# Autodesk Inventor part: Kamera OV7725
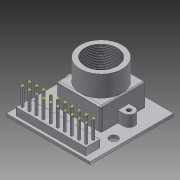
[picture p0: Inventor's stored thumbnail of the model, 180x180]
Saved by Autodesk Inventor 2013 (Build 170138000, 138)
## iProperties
Created: 2012-10
Part Number: Kamera OV7725
Material: Aluminium 6061
Document SubType Name: Modeling
Designer: rYan
Density: 2.71 g/cm^3
Mass: 9.47053 g
Surface Area: 37.4386 cm^2
Volume: 3.49466 cm^3
Author: rYan
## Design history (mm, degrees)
sketch "Skizze1"
  geometry: L1 (-15, 15)-(15, 15); L2 (15, 15)-(15, -15); L3 (15, -15)-(-15, -15); L4 (-15, -15)-(-15, 15); L5 (-21, 0)-(21, 0) reference; L6 (0, -21)-(0, 21) reference; 1 further point
  constraints: 8 end point, 2 parallel, 1 horizontal, 1 perpendicular, 2 other
  dimensions: "d0" = 30 distance of L1.start L1.end; "d1" = 30 distance of L1.end L2.end
extrude "Extrusion1" new body sketch "Skizze1" distance "d2" = 1; taper "d3" = 0 deg
sketch "Skizze2"
  geometry: L1 (-8, 12)-(8, 12); L2 (8, 12)-(8, -4); L3 (8, -4)-(-8, -4); L4 (-8, -4)-(-8, 12); L5 (0, -21)-(0, 21) reference; L6 (15, 15)-(-15, 15) reference; 1 further point
  constraints: 8 end point, 2 parallel, 1 horizontal, 1 perpendicular, 1 other
  dimensions: "d4" = 16 distance of L2.end L3.end; "d5" = 16 distance of L1.end L2.end; "d6" = 3 distance between parallel lines of L6 L1
extrude "Extrusion2" join sketch "Skizze2" distance "d7" = 8; taper "d8" = 0 deg
sketch "Skizze3"
  geometry: L1 (8, 12)-(-8, 12) reference; L2 (-8, 12)-(-8, -4) reference; L3 (8, -4)-(8, 12) reference; L4 (-8, -4)-(8, -4) reference; L5 (0, 12)-(0, -4); L6 (8, 4)-(-8, 4); C1 r 7.5 at (0, 4); 2 further points
  constraints: 5 midpoint, 4 end point, 1 centre point, 1 coincident
  dimensions: "d9" = 15 diameter of C1
extrude "Extrusion3" join sketch "Skizze3" distance "d10" = 7.5; taper "d11" = 0 deg
sketch "Skizze4"
  geometry: L1 (-8, -4)-(-8, 12) reference; L2 (-15, 15)-(-15, -15) reference; L3 (-8, 4)-(-15, 4); L4 (8, 12)-(8, -4) reference; L5 (15, -15)-(15, 15) reference; L6 (8, 4)-(15, 4); L7 (-10, 6)-(-8, 6); L8 (-10, 2)-(-8, 2); L9 (10, 6)-(8, 6); L10 (10, 2)-(8, 2); A1 r 2 centre (-10, 4) between (-10, 6) and (-10, 2); A2 r 2 centre (10, 4) between (10, 2) and (10, 6); 1 further point
  constraints: 12 end point, 8 point on line, 4 point on circle, 4 tangent, 3 parallel, 3 perpendicular, 2 centre point, 2 midpoint
  dimensions: "d12" = 4 diameter of A1; "d13" = 4 diameter of A2; "d16" = 2 distance from line of L1 A1.centre; "d17" = 2 distance from line of L4 A2.centre
extrude "Extrusion4" join sketch "Skizze4" distance "d18" = 4; taper "d19" = 0 deg
sketch "Skizze5"
  geometry: A1 r 2 centre (-10, 4) between (-10, 6) and (-10, 2) reference; A2 r 2 centre (10, 4) between (10, 2) and (10, 6) reference; 3 further points
  constraints: 2 coincident
hole "Bohrung1" sketch "Skizze5" at (-10, 4), (10, 4) diameter "d20" = 1.567; stored, may be unused: countersink angle "d24" = 90 deg, drill point angle "d26" = 118 deg; dims "d21" = 6, "d22" = 4, "d23" = 2, "d25" = 8
sketch "Skizze6"
  geometry: C1 r 7.5 at (0, 0) reference; 2 further points
  constraints: 1 coincident
hole "Bohrung2" sketch "Skizze6" at (0, 0) diameter "d27" = 11.459; stored, may be unused: countersink angle "d31" = 90 deg, drill point angle "d33" = 0 deg; dims "d28" = 8, "d29" = 4, "d30" = 2, "d32" = 12
sketch "Skizze7"
  geometry: L1 (-12.5, -9)-(12.5, -9); L2 (12.5, -9)-(12.5, -14); L3 (12.5, -14)-(-12.5, -14); L4 (-12.5, -14)-(-12.5, -9); L5 (0, -21)-(0, 21); L6 (-21, 0)-(21, 0); 1 further point
  constraints: 12 end point, 2 parallel, 1 horizontal, 1 perpendicular, 1 other
  dimensions: "d34" = 25 distance of L2.end L3.end; "d35" = 5 distance of L1.end L2.end; "d36" = 9 distance between parallel lines of L1 L6
extrude "Extrusion5" join sketch "Skizze7" distance "d37" = 2.7; taper "d38" = 0 deg
sketch "Skizze8"
  geometry: L1 (-11.7, -10)-(-11.1, -10); L2 (-11.1, -10)-(-11.1, -10.6); L3 (-11.1, -10.6)-(-11.7, -10.6); L4 (-11.7, -10.6)-(-11.7, -10); L5 (12.5, -9)-(-12.5, -9) reference; L6 (-12.5, -9)-(-12.5, -14) reference; L7 (-12.5, -14)-(12.5, -14) reference; L8 (12.5, -14)-(12.5, -9) reference; 1 further point
  constraints: 8 end point, 2 parallel, 1 horizontal, 1 perpendicular
  dimensions: "d39" = 0.6 distance of L2.end L3.end; "d40" = 0.6 distance of L1.end L2.end; "d41" = 1 distance between parallel lines of L5 L1; "d42" = 0.8 distance between parallel lines of L6 L4
extrude "Extrusion6" join sketch "Skizze8" distance "d51" = 6.5; taper "d52" = 0 deg
chamfer "Fase1" distance "d53" = 0.15; stored, may be unused: second distance "d54" = 2, angle "d55" = 70 deg
fillet "Rundung1" dims "d62" = 0.5
sketch "Skizze9"
  geometry: L1 (15, 15)-(-15, 15) reference; L2 (-15, 15)-(-15, -15) reference; L3 (15, -15)-(15, 15) reference; 3 further points
  dimensions: "d63" = 3 distance from line of L1 point (-12, 12); "d64" = 3 distance from line of L2 point (-12, 12); "d65" = 18.5 distance from line of point (12, -3.5) L1; "d66" = 3 distance from line of L3 point (12, -3.5)
hole "Bohrung3" sketch "Skizze9" at (-12, 12), (12, -3.5) diameter "d67" = 3; stored, may be unused: countersink angle "d71" = 90 deg, drill point angle "d73" = 118 deg; dims "d68" = 6, "d69" = 4, "d70" = 2, "d72" = 8
workpoint "Arbeitspunkt2"
node "1"
node "2"
node "3"
node "4"
node "5"
node "6"
node "7"
node "8"
node "9"
node "10"
node "11"
node "12"
node "13"
node "14"
node "15"
node "16"
node "17"
node "18"
node "19"
node "20"
node "Volumenkörper1"
pattern_linear "Rechteckige Anordnung1" dims "d58" = 2.54, "d61" = 2.54
node "Projizierte Kontur1"
